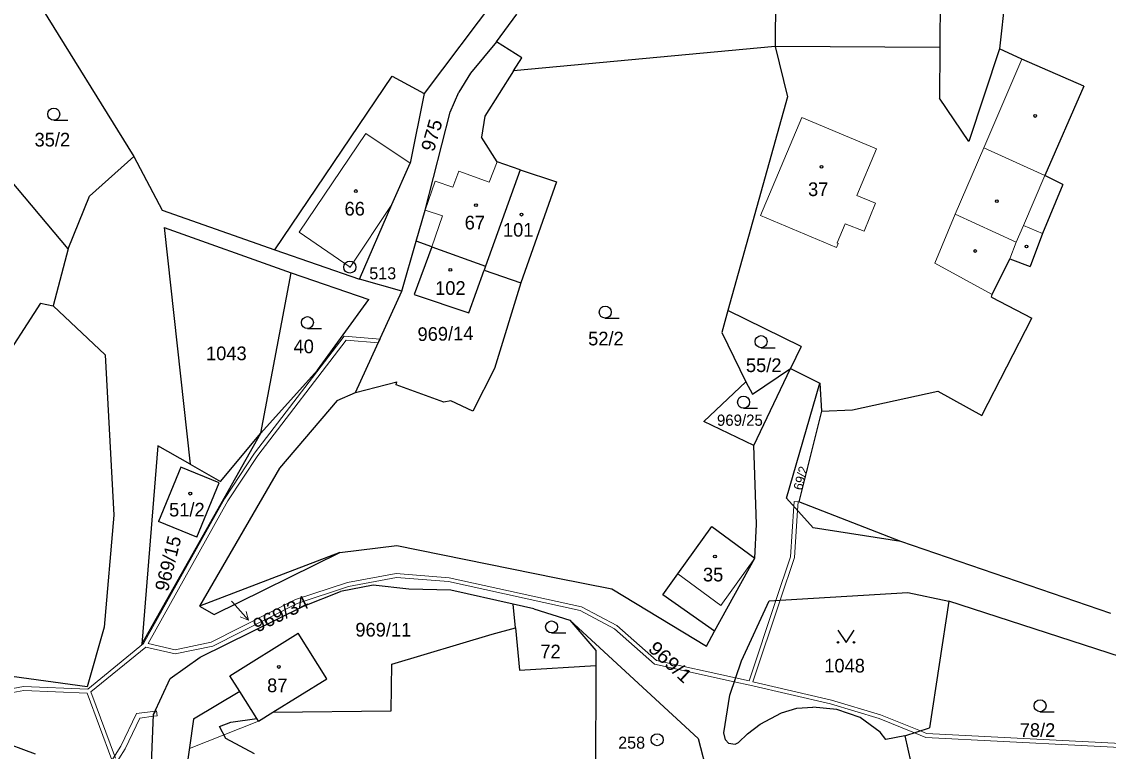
# Model space of a CAD drawing. Extents: x -754970 to -752637, y -970569 to -968179.
# Drawn here: x -753256.8 to -753121.7, y -969385.3 to -969294.5 of the extents above; entities that cross this region are included whole.
import ezdxf
from ezdxf.enums import TextEntityAlignment as Align

# ---------------------------------------------------------------- set-up
doc = ezdxf.new("R2010")
doc.units = 0
doc.header["$LTSCALE"] = 0.68
for name, color, linetype, lineweight in [('1', 7, 'Continuous', 25), ('13', 7, 'Continuous', 13), ('3', 7, 'Continuous', 25), ('4', 7, 'Continuous', 13), ('5', 7, 'Continuous', 25), ('7', 7, 'Continuous', 13), ('8', 7, 'Continuous', 25)]:
    doc.layers.add(name, color=color, linetype=linetype, lineweight=lineweight)
doc.layers.add('2', color=7, linetype='Continuous')

msp = doc.modelspace()

# ---------------------------------------------------------------- linework, layer by layer
at = {"layer": '1'}
for p, q in [((-753132.64, -969274.72), (-753135.25, -969297.94)), ((-753142.57, -969281.15), (-753142.66, -969297.74)), ((-753163.07, -969290.17), (-753163.13, -969297.62)), ((-753254.88, -969291.98), (-753242.89, -969311.34)), ((-753197.46, -969291.06), (-753206.79, -969303.49)), ((-753197.79, -969297.05), (-753195.24, -969293.63)), ((-753197.79, -969297.05), (-753201.01, -969300.97)), ((-753194.65, -969299.05), (-753197.79, -969297.05)), ((-753163.13, -969297.62), (-753195.67, -969300.66)), ((-753142.66, -969297.74), (-753163.13, -969297.62)), ((-753163.13, -969297.62), (-753161.58, -969303.9)), ((-753142.66, -969297.74), (-753142.69, -969304.06)), ((-753135.25, -969297.94), (-753139.03, -969309.47)), ((-753132.45, -969299.21), (-753135.25, -969297.94)), ((-753195.67, -969300.66), (-753194.65, -969299.05)), ((-753124.76, -969302.58), (-753132.45, -969299.21)), ((-753225.35, -969322.95), (-753210.78, -969301.32)), ((-753210.78, -969301.32), (-753206.79, -969303.49)), ((-753201.01, -969300.97), (-753202.46, -969303.33)), ((-753195.67, -969300.66), (-753199.24, -969306.32)), ((-753124.76, -969302.58), (-753129.58, -969313.68)), ((-753206.79, -969303.49), (-753208.51, -969312.14)), ((-753203.56, -969305.8), (-753202.46, -969303.33)), ((-753161.58, -969303.9), (-753169.01, -969330.48)), ((-753139.03, -969309.47), (-753142.69, -969304.06)), ((-753206.65, -969317.99), (-753203.56, -969305.8)), ((-753199.24, -969306.32), (-753199.66, -969308.9)), ((-753197.71, -969311.97), (-753199.66, -969308.9)), ((-753248.39, -969316.24), (-753242.89, -969311.34)), ((-753242.89, -969311.34), (-753239.38, -969318)), ((-753210.82, -969317.31), (-753208.51, -969312.14)), ((-753194.84, -969312.98), (-753197.71, -969311.97)), ((-753251.04, -969322.82), (-753259.09, -969313.23)), ((-753194.84, -969312.98), (-753199.14, -969324.98)), ((-753194.84, -969312.98), (-753190.32, -969314.49)), ((-753190.32, -969314.49), (-753194.75, -969327.06)), ((-753127.34, -969314.79), (-753129.87, -969320.92)), ((-753127.34, -969314.79), (-753129.58, -969313.68)), ((-753251.04, -969322.82), (-753248.39, -969316.24)), ((-753214.83, -969326.59), (-753210.82, -969317.31)), ((-753239.38, -969318), (-753225.35, -969322.95)), ((-753207.76, -969321.86), (-753206.65, -969317.99)), ((-753239.11, -969320.16), (-753235.87, -969349.6)), ((-753239.11, -969320.16), (-753223.3, -969325.8)), ((-753129.87, -969320.92), (-753131.41, -969325.01)), ((-753251.04, -969322.82), (-753252.91, -969329.89)), ((-753225.35, -969322.95), (-753214.83, -969326.59)), ((-753209.54, -969328.07), (-753207.76, -969321.86)), ((-753205.83, -969322.56), (-753208.03, -969328.51)), ((-753205.83, -969322.56), (-753207.76, -969321.86)), ((-753136.16, -969328.5), (-753133.95, -969324.04)), ((-753133.95, -969324.04), (-753131.41, -969325.01)), ((-753227.11, -969345.74), (-753223.3, -969325.8)), ((-753223.3, -969325.8), (-753213.68, -969329.12)), ((-753201.23, -969330.78), (-753199.31, -969325.45)), ((-753199.31, -969325.45), (-753194.75, -969327.06)), ((-753209.54, -969328.07), (-753214.83, -969326.59)), ((-753194.75, -969327.06), (-753198.03, -969337.7)), ((-753215.3, -969340.7), (-753209.54, -969328.07)), ((-753208.03, -969328.51), (-753201.23, -969330.78)), ((-753136.23, -969328.84), (-753136.16, -969328.5)), ((-753254.49, -969329.58), (-753263.43, -969343.39)), ((-753254.49, -969329.58), (-753252.91, -969329.89)), ((-753220.04, -969337.89), (-753213.68, -969329.12)), ((-753136.23, -969328.84), (-753131.21, -969331.43)), ((-753252.91, -969329.89), (-753246.44, -969335.99)), ((-753169.01, -969330.48), (-753169.78, -969333.21)), ((-753159.91, -969334.97), (-753169.01, -969330.48)), ((-753137.42, -969343.54), (-753131.21, -969331.43)), ((-753169.78, -969333.21), (-753166.8, -969339.36)), ((-753159.91, -969334.97), (-753161.21, -969337.68)), ((-753246.44, -969335.99), (-753245.39, -969355.94)), ((-753227.11, -969345.74), (-753220.04, -969337.89)), ((-753198.03, -969337.7), (-753200.74, -969342.99)), ((-753165.94, -969340.89), (-753161.21, -969337.68)), ((-753165.8, -969347.26), (-753161.21, -969337.68)), ((-753161.21, -969337.68), (-753157.56, -969339.53)), ((-753215.3, -969340.7), (-753210.17, -969339.34)), ((-753210.25, -969339.74), (-753210.17, -969339.34)), ((-753204.35, -969341.88), (-753210.25, -969339.74)), ((-753166.8, -969339.36), (-753171.99, -969344.31)), ((-753166.8, -969339.36), (-753165.94, -969340.89)), ((-753161.74, -969353.83), (-753157.56, -969339.53)), ((-753157.56, -969339.53), (-753157.37, -969343)), ((-753153.51, -969342.85), (-753142.91, -969340.52)), ((-753142.91, -969340.52), (-753137.42, -969343.54)), ((-753217.58, -969341.67), (-753224.75, -969350.12)), ((-753217.58, -969341.67), (-753215.3, -969340.7)), ((-753203.45, -969341.71), (-753204.35, -969341.88)), ((-753200.74, -969342.99), (-753203.45, -969341.71)), ((-753157.37, -969343), (-753160.2, -969354.31)), ((-753157.37, -969343), (-753153.51, -969342.85)), ((-753165.8, -969347.26), (-753171.99, -969344.31)), ((-753241.9, -969372), (-753227.11, -969345.74)), ((-753232.09, -969351.74), (-753227.11, -969345.74)), ((-753239.92, -969347.31), (-753241.9, -969372)), ((-753235.87, -969349.6), (-753239.92, -969347.31)), ((-753165.44, -969357.07), (-753165.8, -969347.26)), ((-753237.06, -969349.99), (-753239.8, -969356.75)), ((-753232.28, -969351.93), (-753237.06, -969349.99)), ((-753235.87, -969349.6), (-753232.09, -969351.74)), ((-753224.75, -969350.12), (-753234.71, -969367.26)), ((-753235.06, -969358.67), (-753232.28, -969351.93)), ((-753161.74, -969353.83), (-753158.39, -969357.52)), ((-753147.49, -969359.23), (-753160.2, -969354.31)), ((-753245.39, -969355.94), (-753246.57, -969369.88)), ((-753235.06, -969358.67), (-753239.8, -969356.75)), ((-753175.24, -969363.26), (-753171, -969357.37)), ((-753171, -969357.37), (-753165.68, -969361.31)), ((-753165.68, -969361.31), (-753165.44, -969357.07)), ((-753147.49, -969359.23), (-753158.39, -969357.52)), ((-753121.39, -969368.19), (-753147.49, -969359.23)), ((-753217.25, -969360.6), (-753234.71, -969367.26)), ((-753232.91, -969368.32), (-753217.25, -969360.6)), ((-753217.25, -969360.6), (-753210.17, -969359.72)), ((-753210.17, -969359.72), (-753190.37, -969363.73)), ((-753170.67, -969370.4), (-753165.68, -969361.31)), ((-753177.09, -969365.88), (-753175.24, -969363.26)), ((-753213.13, -969364.67), (-753217.19, -969365.46)), ((-753208.67, -969365.14), (-753213.13, -969364.67)), ((-753190.37, -969363.73), (-753183.44, -969365.1)), ((-753221.77, -969367.26), (-753217.19, -969365.46)), ((-753203.45, -969365.28), (-753208.67, -969365.14)), ((-753195.72, -969367.02), (-753203.45, -969365.28)), ((-753183.44, -969365.1), (-753171.68, -969372.24)), ((-753170.67, -969370.4), (-753177.09, -969365.88)), ((-753163.89, -969366.61), (-753146.65, -969365.56)), ((-753146.65, -969365.56), (-753141.52, -969366.63)), ((-753234.71, -969367.26), (-753232.91, -969368.32)), ((-753234.62, -969373.63), (-753221.77, -969367.26)), ((-753195.44, -969369.97), (-753195.72, -969367.02)), ((-753193.13, -969367.6), (-753195.72, -969367.02)), ((-753193.13, -969367.6), (-753188.65, -969369.02)), ((-753167.33, -969374.07), (-753163.89, -969366.61)), ((-753141.52, -969366.63), (-753143.93, -969382.43)), ((-753112.53, -969376.1), (-753141.52, -969366.63)), ((-753188.65, -969369.02), (-753172.69, -969383.72)), ((-753188.65, -969369.02), (-753185.44, -969372.79)), ((-753246.57, -969369.88), (-753248.7, -969377.33)), ((-753198.33, -969370.76), (-753195.44, -969369.97)), ((-753195.44, -969369.97), (-753194.94, -969375.23)), ((-753171.68, -969372.24), (-753170.67, -969370.4)), ((-753230.93, -969375.96), (-753222.45, -969370.62)), ((-753218.87, -969376.33), (-753222.45, -969370.62)), ((-753210.79, -969374.47), (-753198.33, -969370.76)), ((-753185.44, -969372.79), (-753185.44, -969374.64)), ((-753238.36, -969376.29), (-753234.62, -969373.63)), ((-753168.79, -969378.34), (-753167.33, -969374.07)), ((-753210.87, -969380.3), (-753210.79, -969374.47)), ((-753194.94, -969375.23), (-753185.44, -969374.64)), ((-753185.44, -969374.64), (-753185.48, -969388.33)), ((-753248.7, -969377.33), (-753258.04, -969376.04)), ((-753240.42, -969380.77), (-753238.36, -969376.29)), ((-753229.71, -969377.89), (-753230.93, -969375.96)), ((-753225.59, -969380.48), (-753218.87, -969376.33)), ((-753229.71, -969377.89), (-753235.46, -969381.34)), ((-753227.59, -969381.27), (-753229.71, -969377.89)), ((-753169.53, -969383.05), (-753168.79, -969378.34)), ((-753160.44, -969379.97), (-753158.43, -969379.82)), ((-753155.45, -969380.12), (-753158.43, -969379.82)), ((-753240.68, -969386.84), (-753240.42, -969380.77)), ((-753227.39, -969381.59), (-753225.59, -969380.48)), ((-753225.59, -969380.48), (-753210.87, -969380.3)), ((-753165.01, -969381.94), (-753162.36, -969380.55)), ((-753162.36, -969380.55), (-753160.44, -969379.97)), ((-753152.57, -969381.14), (-753155.45, -969380.12)), ((-753150.08, -969382.94), (-753152.57, -969381.14)), ((-753235.46, -969381.34), (-753237.34, -969394.41)), ((-753232.22, -969382.26), (-753230.84, -969381.69)), ((-753231.44, -969383.72), (-753232.22, -969382.26)), ((-753230.84, -969381.69), (-753227.59, -969381.27)), ((-753227.39, -969381.59), (-753227.59, -969381.27)), ((-753166.56, -969383.17), (-753165.01, -969381.94)), ((-753146.99, -969383.42), (-753143.93, -969382.43)), ((-753263, -969382.73), (-753255.16, -969385.63)), ((-753227.87, -969385.66), (-753231.44, -969383.72)), ((-753172.69, -969383.72), (-753169.78, -969395.14)), ((-753169.29, -969383.91), (-753169.53, -969383.05)), ((-753169.29, -969383.91), (-753168.92, -969384.34)), ((-753167.7, -969384.22), (-753166.56, -969383.17)), ((-753149.39, -969383.87), (-753150.08, -969382.94)), ((-753146.99, -969383.42), (-753149.39, -969383.87)), ((-753146.99, -969383.42), (-753144.71, -969393.8)), ((-753168.92, -969384.34), (-753168.11, -969384.46)), ((-753168.11, -969384.46), (-753167.7, -969384.22))]:
    msp.add_line(p, q, dxfattribs=at)
msp.add_lwpolyline([(-753205.83, -969322.56), (-753199.14, -969324.98), (-753199.31, -969325.45)], dxfattribs=at)
at = {"layer": '13'}
for points in [[(-753216.71, -969333.67), (-753227.88, -969348.22), (-753231.61, -969353.93), (-753241.67, -969371.93), (-753248.61, -969377.62), (-753256.59, -969377.26), (-753258.6, -969377.63)], [(-753168.06, -969376.2), (-753177.9, -969374.05), (-753182.84, -969369.66), (-753187.2, -969367.34), (-753203.68, -969363.73), (-753210.26, -969363.21), (-753216.31, -969364.33), (-753222.78, -969366.45), (-753233.25, -969371.76), (-753237.76, -969372.71), (-753241.09, -969371.92), (-753231.18, -969354.18), (-753227.47, -969348.51), (-753216.48, -969334.19), (-753212.48, -969334.52), (-753212.26, -969334.03), (-753216.71, -969333.67)], [(-753115.28, -969384.61), (-753144.3, -969383.11), (-753145.08, -969382.8), (-753150.02, -969380.8), (-753156.13, -969378.96), (-753165.89, -969376.68), (-753162.5, -969366.53), (-753160.73, -969361.23), (-753160.35, -969355.36), (-753160.29, -969354.3), (-753160.78, -969354.26), (-753160.82, -969354.84), (-753161.23, -969361.14), (-753163.04, -969366.56), (-753166.38, -969376.57), (-753168.06, -969376.2)], [(-753245.17, -969386.19), (-753248.23, -969377.95), (-753241.41, -969372.36), (-753237.76, -969373.22), (-753233.08, -969372.24), (-753222.59, -969366.92), (-753216.19, -969364.81), (-753210.23, -969363.72), (-753203.76, -969364.22), (-753187.37, -969367.81), (-753183.13, -969370.08), (-753178.13, -969374.51), (-753168.22, -969376.68), (-753166.27, -969377.1), (-753156.26, -969379.44), (-753150.19, -969381.27), (-753145.82, -969383.04), (-753144.41, -969383.61), (-753115.44, -969385.1)], [(-753258.39, -969378.1), (-753256.56, -969377.76), (-753248.7, -969378.11), (-753245.62, -969386.41)], [(-753246.33, -969388.75), (-753243.98, -969385.01), (-753242.14, -969381.2), (-753240.43, -969380.96), (-753240.42, -969380.77), (-753240.21, -969380.32), (-753242.54, -969380.64), (-753244.5, -969384.71), (-753246.81, -969388.39)]]:
    msp.add_lwpolyline(points, dxfattribs=at)
for points in [[(-753235.46, -969381.34), (-753235.98, -969384.98), (-753227.39, -969381.59), (-753227.59, -969381.27), (-753229.71, -969377.89)], [(-753240.05, -969380.3), (-753240.21, -969380.32), (-753240.42, -969380.77), (-753240.43, -969380.96), (-753239.97, -969380.9)]]:
    msp.add_lwpolyline(points, close=True, dxfattribs=at)
at = {"layer": '3'}
for p, q in [((-753252.843, -969306.8), (-753251.093, -969306.8)), ((-753184.263, -969331.43), (-753182.513, -969331.43)), ((-753221.303, -969332.74), (-753219.553, -969332.74)), ((-753164.883, -969335.11), (-753163.133, -969335.11)), ((-753167.063, -969342.64), (-753165.313, -969342.64)), ((-753190.933, -969370.61), (-753189.183, -969370.61)), ((-753130.193, -969380.41), (-753128.443, -969380.41))]:
    msp.add_line(p, q, dxfattribs=at)
msp.add_lwpolyline([(-753155.32, -969370.279), (-753154.32, -969371.78), (-753153.32, -969370.279)], dxfattribs=at)
for centre, radius in [((-753252.8429, -969306.0498), 0.75), ((-753184.2629, -969330.6798), 0.75), ((-753221.3029, -969331.9898), 0.75), ((-753164.8829, -969334.3598), 0.75), ((-753167.0629, -969341.8898), 0.75), ((-753190.9329, -969369.8598), 0.75), ((-753155.32, -969371.7795), 0.1), ((-753153.32, -969371.7795), 0.1), ((-753130.1929, -969379.6598), 0.75)]:
    msp.add_circle(centre, radius, dxfattribs=at)
at = {"layer": '4'}
for p, q in [((-753132.45, -969299.21), (-753137.19, -969310.26)), ((-753159.82, -969306.47), (-753164.97, -969318.67)), ((-753159.82, -969306.47), (-753150.55, -969310.37)), ((-753222.33, -969320.75), (-753214.04, -969308.47)), ((-753208.51, -969312.14), (-753214.04, -969308.47)), ((-753152.97, -969316.18), (-753150.55, -969310.37)), ((-753137.19, -969310.26), (-753140.74, -969318.51)), ((-753129.58, -969313.68), (-753137.19, -969310.26)), ((-753197.71, -969311.97), (-753198.7, -969314.5)), ((-753203.21, -969315.13), (-753202.49, -969313.16)), ((-753198.7, -969314.5), (-753202.49, -969313.16)), ((-753205.41, -969314.38), (-753203.21, -969315.13)), ((-753129.58, -969313.68), (-753132.26, -969319.9)), ((-753152.97, -969316.18), (-753150.65, -969317.11)), ((-753210.82, -969317.31), (-753216, -969325.09)), ((-753150.65, -969317.11), (-753152.07, -969320.6)), ((-753155.49, -969322.63), (-753164.97, -969318.67)), ((-753143.28, -969324.59), (-753140.74, -969318.51)), ((-753133.16, -969321.99), (-753140.74, -969318.51)), ((-753155.41, -969322.06), (-753154.43, -969319.69)), ((-753152.07, -969320.6), (-753154.43, -969319.69)), ((-753133.16, -969321.99), (-753132.26, -969319.9)), ((-753129.87, -969320.92), (-753132.26, -969319.9)), ((-753216, -969325.09), (-753222.33, -969320.75)), ((-753155.49, -969322.63), (-753155.29, -969322.13)), ((-753155.29, -969322.13), (-753155.41, -969322.06)), ((-753133.95, -969324.04), (-753133.16, -969321.99)), ((-753136.16, -969328.5), (-753143.28, -969324.59)), ((-753165.68, -969361.31), (-753169.88, -969367.19)), ((-753169.88, -969367.19), (-753175.24, -969363.26))]:
    msp.add_line(p, q, dxfattribs=at)
msp.add_lwpolyline([(-753205.83, -969322.56), (-753204.49, -969318.7), (-753206.65, -969317.99), (-753205.41, -969314.38)], dxfattribs=at)
at = {"layer": '5'}
for centre in [(-753130.7968, -969306.2792), (-753157.3768, -969312.6092), (-753215.2668, -969315.6192), (-753200.3368, -969317.3692), (-753135.5768, -969316.8692), (-753194.6668, -969318.5492), (-753138.2568, -969323.0792), (-753131.8668, -969322.5192), (-753203.5268, -969325.4292), (-753235.8668, -969353.2692), (-753170.6168, -969361.0892), (-753224.8468, -969374.8392)]:
    msp.add_circle(centre, 0.175, dxfattribs=at)
at = {"layer": '7'}
msp.add_line((-753228.622, -969369), (-753228.92, -969367.921), dxfattribs=at)
msp.add_lwpolyline([(-753230.75, -969366.64), (-753230.63, -969366.77), (-753228.622, -969369), (-753229.664, -969368.591)], dxfattribs=at)
at = {"layer": '8'}
for centre, radius in [((-753216.03, -969325.0798), 0.75), ((-753216.03, -969325.0798), 0.03), ((-753177.81, -969383.8898), 0.75), ((-753177.81, -969383.8898), 0.03)]:
    msp.add_circle(centre, radius, dxfattribs=at)

# ---------------------------------------------------------------- texts
at = {"layer": '2'}
for s, rotation, width, p in [('975', 74, 1.05, (-753205.0265, -969308.9068)), ('969/1', 317, 1.1, (-753176.7547, -969374.8454))]:
    msp.add_text(s, height=1.7, rotation=rotation, dxfattribs=dict(at, width=width)).set_placement(p, align=Align.CENTER)
for s, height, p in [('35/2', 1.7, (-753253.019, -969310.075)), ('37', 1.7, (-753157.779, -969316.245)), ('66', 1.7, (-753215.419, -969318.665)), ('67', 1.7, (-753200.479, -969320.395)), ('101', 1.7, (-753195.089, -969321.295)), ('102', 1.7, (-753203.519, -969328.535)), ('52/2', 1.7, (-753184.179, -969334.825)), ('1043', 1.7, (-753231.38, -969336.665)), ('40', 1.7, (-753221.759, -969335.805)), ('55/2', 1.7, (-753164.559, -969338.145)), ('969/25', 1.394, (-753167.52, -969344.828)), ('51/2', 1.7, (-753236.289, -969356.115)), ('35', 1.7, (-753170.849, -969364.195)), ('969/11', 1.7, (-753211.86, -969371.055)), ('72', 1.7, (-753191.069, -969373.765)), ('1048', 1.7, (-753154.5, -969375.525)), ('87', 1.7, (-753225.049, -969377.975)), ('78/2', 1.7, (-753130.509, -969383.545))]:
    msp.add_text(s, height=height, dxfattribs=at).set_placement(p, align=Align.CENTER)
for s, height, rotation, p in [('969/14', 1.7, 1, (-753204.1148, -969334.2244)), ('69/2', 1.14, 75, (-753159.404, -969351.488)), ('969/15', 1.7, 76, (-753237.8014, -969362.1581))]:
    msp.add_text(s, height=height, rotation=rotation, dxfattribs=at).set_placement(p, align=Align.CENTER)
at = {"layer": '2', "width": 1.05}
msp.add_text('969/34', height=1.7, rotation=26, dxfattribs=at).set_placement((-753227.525, -969370.585))
at = {"layer": '8'}
for s, p in [('513', (-753210.261, -969326.606)), ('258', (-753179.309, -969385.007))]:
    msp.add_text(s, height=1.5, dxfattribs=at).set_placement(p, align=Align.RIGHT)

doc.saveas('drawing.dxf')
